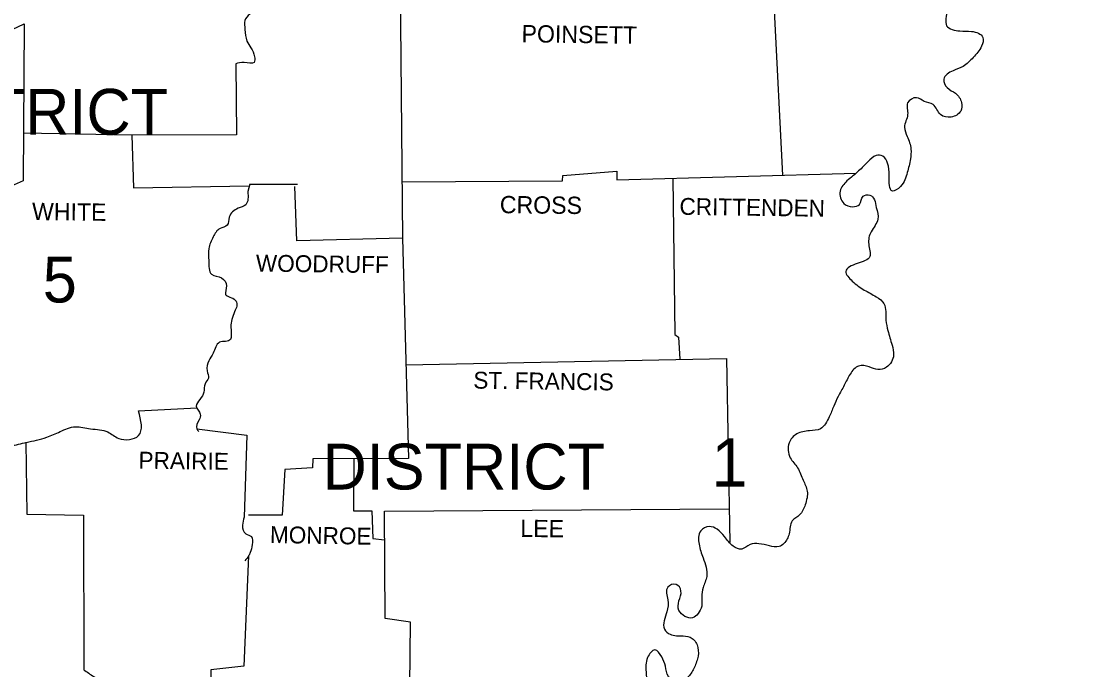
# Model space of a CAD drawing. Extents: x 3046 to 131673, y -8885 to 10756.
# Drawn here: x 105176 to 107768, y 7566 to 9143 of the extents above; entities that cross this region are included whole.
import ezdxf

# ---------------------------------------------------------------- set-up
doc = ezdxf.new("R2010")
doc.units = 0
for name, color, linetype in [('1', 7, 'Continuous'), ('2', 7, 'Continuous'), ('3', 7, 'Continuous')]:
    doc.layers.add(name, color=color, linetype=linetype)

msp = doc.modelspace()

# ---------------------------------------------------------------- linework, layer by layer
at = {"layer": '1'}
msp.add_line((105732.6, 8746.6), (105849, 8746.6), dxfattribs=at)
msp.add_line((105732.6, 8746.6), (105849, 8746.6), dxfattribs=at)
for points in [[(105635.7, 10322.8), (105632.8, 10299.3), (105652.4, 10296.4), (105651.4, 10284.6), (105673.9, 10279.7), (105675.8, 10264.1), (105686.6, 10257.2), (105689.5, 10210.3), (105745.3, 10204.4), (105745.3, 10162.3), (105765.9, 10159.4), (105765.9, 10142.7), (105783.5, 10137.9), (105782.5, 10081.1), (105798.1, 10078.2), (105802.1, 9950), (105718.9, 9942.2), (105719.9, 9914.8), (105694.4, 9913.8), (105703.2, 9408.9), (106097.5, 9400.1), (106104.4, 8615.5), (105847.1, 8608.6), (105842.2, 8740.7)], [(105635.7, 10322.8), (105632.8, 10299.3), (105652.4, 10296.4), (105651.4, 10284.6), (105673.9, 10279.7), (105675.8, 10264.1), (105686.6, 10257.2), (105689.5, 10210.3), (105745.3, 10204.4), (105745.3, 10162.3), (105765.9, 10159.4), (105765.9, 10142.7), (105783.5, 10137.9), (105782.5, 10081.1), (105798.1, 10078.2), (105802.1, 9950), (105718.9, 9942.2), (105719.9, 9914.8), (105694.4, 9913.8), (105703.2, 9408.9), (106097.5, 9400.1), (106104.4, 8615.5), (105847.1, 8608.6), (105842.2, 8740.7)], [(106992.5, 9598.7), (107009.4, 9169.2), (107029.3, 8768.4)], [(106992.5, 9598.7), (107009.4, 9169.2), (107029.3, 8768.4)], [(104637.7, 9119.3), (105140.6, 9116.4), (105183.7, 9136.9), (105180.8, 8754.4), (105151.4, 8741.7), (105125, 8719.2), (105116.2, 8710.4), (105115.2, 8600.8), (104801.1, 8598.8)], [(104637.7, 9119.3), (105140.6, 9116.4), (105183.7, 9136.9), (105180.8, 8754.4), (105151.4, 8741.7), (105125, 8719.2), (105116.2, 8710.4), (105115.2, 8600.8), (104801.1, 8598.8)], [(105698.3, 9039.1), (105700.3, 8866.9), (105445.9, 8865.9), (105181.7, 8870.9)], [(105698.3, 9039.1), (105700.3, 8866.9), (105445.9, 8865.9), (105181.7, 8870.9)], [(105445.9, 8865.9), (105449.8, 8737.8), (105731.5, 8742.8)], [(105445.9, 8865.9), (105449.8, 8737.8), (105731.5, 8742.8)], [(106103.2, 8752.4), (106493.8, 8754.4), (106494.8, 8768.1), (106625.9, 8777.9), (106625.9, 8757.3), (107208.7, 8773.3)], [(106103.2, 8752.4), (106493.8, 8754.4), (106494.8, 8768.1), (106625.9, 8777.9), (106625.9, 8757.3), (107208.7, 8773.3)], [(106762.8, 8761.1), (106767.7, 8380.6), (106776.5, 8374.8), (106779.7, 8320.6)], [(106762.8, 8761.1), (106767.7, 8380.6), (106776.5, 8374.8), (106779.7, 8320.6)], [(105732.6, 8746.6), (105727.7, 8728.9)], [(105732.6, 8746.6), (105727.7, 8728.9)], [(106104.4, 8615.5), (106119.1, 8079.3), (105886.2, 8078.3), (105885.2, 8056.8), (105817.7, 8052.9), (105811.8, 7941.3), (105729.7, 7941.3)], [(106104.4, 8615.5), (106119.1, 8079.3), (105886.2, 8078.3), (105885.2, 8056.8), (105817.7, 8052.9), (105811.8, 7941.3), (105729.7, 7941.3)], [(106112.8, 8307.2), (106893, 8322.9)], [(106112.8, 8307.2), (106893, 8322.9)], [(106893, 8322.9), (106901.2, 7874.7)], [(106893, 8322.9), (106901.2, 7874.7)], [(105461.6, 8195.7), (105603.4, 8202.6)], [(105461.6, 8195.7), (105603.4, 8202.6)], [(105603.4, 8151.7), (105725.7, 8136), (105718.9, 7936.4)], [(105603.4, 8151.7), (105725.7, 8136), (105718.9, 7936.4)], [(105187.6, 8119.4), (105189.6, 7944.3), (105327.5, 7941.3), (105328.5, 7565.6)], [(105187.6, 8119.4), (105189.6, 7944.3), (105327.5, 7941.3), (105328.5, 7565.6)], [(105986, 8078.7), (105985, 7952.1), (106030, 7952.1), (106032, 7884.6), (106060.9, 7881.6)], [(105986, 8078.7), (105985, 7952.1), (106030, 7952.1), (106032, 7884.6), (106060.9, 7881.6)], [(106116.1, 7084.2), (106192.4, 7089.1), (106191.5, 7287.8), (106120, 7292.6), (106123.9, 7681.1), (106062.3, 7689.9), (106060.4, 7951.1), (106899.7, 7957)], [(106116.1, 7084.2), (106192.4, 7089.1), (106191.5, 7287.8), (106120, 7292.6), (106123.9, 7681.1), (106062.3, 7689.9), (106060.4, 7951.1), (106899.7, 7957)], [(105729.7, 7842.5), (105717.9, 7574.4), (105637.7, 7565.6), (105639.6, 7486.4), (105671.9, 7487.3), (105672.9, 7460), (105716.9, 7455.1), (105718.4, 7407.8)], [(105729.7, 7842.5), (105717.9, 7574.4), (105637.7, 7565.6), (105639.6, 7486.4), (105671.9, 7487.3), (105672.9, 7460), (105716.9, 7455.1), (105718.4, 7407.8)]]:
    msp.add_lwpolyline(points, dxfattribs=at)
for points in [[(107630.7, 9631), (107641.5, 9632), (107674.7, 9596.8), (107689.4, 9567.4), (107710.9, 9550.8), (107735.4, 9542), (107754, 9519.5), (107766.7, 9495), (107759.8, 9473.5), (107732.4, 9471.6), (107702.1, 9466.7), (107672.8, 9467.6), (107649.3, 9448.1), (107670.8, 9421.7), (107699.2, 9397.2), (107707, 9370.8), (107691.4, 9345.3), (107660, 9331.6), (107629.7, 9319.9), (107602.3, 9296.4), (107589.6, 9273.9), (107559.3, 9264.1), (107528, 9255.3), (107500.6, 9252.4), (107469.3, 9246.5), (107438.9, 9231.8), (107426.2, 9206.4), (107430.1, 9170.2), (107429.1, 9132.1), (107461.4, 9119.3), (107489.8, 9118.4), (107517.2, 9103.7), (107514.3, 9082.2), (107493.7, 9054.8), (107469.3, 9033.2), (107444.8, 9022.5), (107422.3, 9001.9), (107430.1, 8981.4), (107450.7, 8967.7), (107465.3, 8945.2), (107463.4, 8924.6), (107439.9, 8910), (107414.5, 8915.8), (107395.9, 8940.3), (107374.4, 8948.1), (107355.8, 8956.9), (107334.2, 8944.2), (107334.2, 8915.8), (107326.4, 8885.5), (107333.3, 8863), (107342.1, 8831.7), (107341.1, 8808.2), (107333.3, 8774.9), (107316.6, 8740.7), (107297.1, 8729.9), (107289.2, 8767.1), (107285.3, 8797.4), (107273.6, 8815), (107257.9, 8816), (107237.4, 8801.3), (107214.9, 8778.8), (107186.5, 8754.4), (107169.9, 8729.9), (107178.7, 8699.6), (107200.2, 8691.8), (107216.8, 8697.6), (107225.6, 8717.2), (107242.3, 8720.1), (107257.9, 8689.8)], [(107630.7, 9631), (107641.5, 9632), (107674.7, 9596.8), (107689.4, 9567.4), (107710.9, 9550.8), (107735.4, 9542), (107754, 9519.5), (107766.7, 9495), (107759.8, 9473.5), (107732.4, 9471.6), (107702.1, 9466.7), (107672.8, 9467.6), (107649.3, 9448.1), (107670.8, 9421.7), (107699.2, 9397.2), (107707, 9370.8), (107691.4, 9345.3), (107660, 9331.6), (107629.7, 9319.9), (107602.3, 9296.4), (107589.6, 9273.9), (107559.3, 9264.1), (107528, 9255.3), (107500.6, 9252.4), (107469.3, 9246.5), (107438.9, 9231.8), (107426.2, 9206.4), (107430.1, 9170.2), (107429.1, 9132.1), (107461.4, 9119.3), (107489.8, 9118.4), (107517.2, 9103.7), (107514.3, 9082.2), (107493.7, 9054.8), (107469.3, 9033.2), (107444.8, 9022.5), (107422.3, 9001.9), (107430.1, 8981.4), (107450.7, 8967.7), (107465.3, 8945.2), (107463.4, 8924.6), (107439.9, 8910), (107414.5, 8915.8), (107395.9, 8940.3), (107374.4, 8948.1), (107355.8, 8956.9), (107334.2, 8944.2), (107334.2, 8915.8), (107326.4, 8885.5), (107333.3, 8863), (107342.1, 8831.7), (107341.1, 8808.2), (107333.3, 8774.9), (107316.6, 8740.7), (107297.1, 8729.9), (107289.2, 8767.1), (107285.3, 8797.4), (107273.6, 8815), (107257.9, 8816), (107237.4, 8801.3), (107214.9, 8778.8), (107186.5, 8754.4), (107169.9, 8729.9), (107178.7, 8699.6), (107200.2, 8691.8), (107216.8, 8697.6), (107225.6, 8717.2), (107242.3, 8720.1), (107257.9, 8689.8)], [(105878.8, 9405.1), (105861.7, 9361), (105848, 9331.6), (105839.2, 9306.2), (105820.6, 9291.5), (105814.8, 9277.8), (105798.1, 9272), (105785.4, 9252.4), (105779.5, 9234.8), (105765.9, 9227), (105759, 9205.4), (105746.3, 9193.7), (105747.3, 9174.1), (105732.6, 9160.4), (105720.8, 9144.8), (105720.8, 9123.2), (105725.7, 9094.9), (105735.5, 9078.2), (105744.3, 9056.7), (105743.3, 9043), (105718.9, 9043), (105698.3, 9039.1)], [(105878.8, 9405.1), (105861.7, 9361), (105848, 9331.6), (105839.2, 9306.2), (105820.6, 9291.5), (105814.8, 9277.8), (105798.1, 9272), (105785.4, 9252.4), (105779.5, 9234.8), (105765.9, 9227), (105759, 9205.4), (105746.3, 9193.7), (105747.3, 9174.1), (105732.6, 9160.4), (105720.8, 9144.8), (105720.8, 9123.2), (105725.7, 9094.9), (105735.5, 9078.2), (105744.3, 9056.7), (105743.3, 9043), (105718.9, 9043), (105698.3, 9039.1)], [(105727.7, 8728.9), (105722.8, 8696.7), (105704.2, 8687.9), (105682.7, 8666.3), (105677.8, 8646.8), (105660.2, 8638.9), (105643.6, 8618.4), (105632.8, 8590), (105632.8, 8560.7), (105639.6, 8527.4), (105664.1, 8518.6), (105675.8, 8499), (105673.9, 8478.5), (105697.4, 8464.8), (105701.3, 8453), (105697.4, 8440.3), (105686.6, 8404.1), (105687.6, 8379.7), (105685.6, 8368.9), (105659.2, 8362), (105643.6, 8335.6), (105632.8, 8317), (105628.9, 8292.6), (105631.8, 8275), (105624, 8261.3), (105621, 8240.7), (105611.3, 8223.1), (105602.5, 8206.5), (105612.2, 8186.9), (105609.3, 8173.2), (105603.4, 8151.7), (105608.3, 8144.8)], [(105727.7, 8728.9), (105722.8, 8696.7), (105704.2, 8687.9), (105682.7, 8666.3), (105677.8, 8646.8), (105660.2, 8638.9), (105643.6, 8618.4), (105632.8, 8590), (105632.8, 8560.7), (105639.6, 8527.4), (105664.1, 8518.6), (105675.8, 8499), (105673.9, 8478.5), (105697.4, 8464.8), (105701.3, 8453), (105697.4, 8440.3), (105686.6, 8404.1), (105687.6, 8379.7), (105685.6, 8368.9), (105659.2, 8362), (105643.6, 8335.6), (105632.8, 8317), (105628.9, 8292.6), (105631.8, 8275), (105624, 8261.3), (105621, 8240.7), (105611.3, 8223.1), (105602.5, 8206.5), (105612.2, 8186.9), (105609.3, 8173.2), (105603.4, 8151.7), (105608.3, 8144.8)], [(107257.9, 8689.8), (107261.8, 8661.4), (107245.2, 8631.1), (107239.3, 8600.8), (107242.3, 8570.4), (107211, 8553.8), (107183.6, 8534.2), (107199.2, 8510.8), (107228.6, 8489.2), (107257.9, 8472.6), (107276.5, 8456), (107281.4, 8415.9), (107286.3, 8390.4), (107296.1, 8355.2), (107300, 8330.7), (107282.4, 8301.4), (107261.8, 8295.5), (107240.3, 8302.4), (107214.9, 8304.3), (107194.3, 8284.8), (107179.6, 8257.4), (107165, 8230), (107154.2, 8206.5), (107143.4, 8181), (107121.9, 8151.7), (107095.5, 8146.8), (107064.2, 8139), (107045.6, 8117.4), (107048.5, 8081.2), (107066.2, 8056.8), (107079.9, 8026.5), (107089.6, 8000), (107084.7, 7966.8), (107071, 7942.3), (107053.4, 7927.6), (107045.6, 7896.3), (107032.9, 7872.8), (107021.1, 7865), (106997.7, 7867), (106972.2, 7871.9), (106950.7, 7869.9), (106930.2, 7859.1), (106909.6, 7866), (106888.1, 7889.5), (106870.5, 7907.1), (106850.9, 7913.9), (106830.4, 7903.2), (106826.4, 7870.9), (106836.2, 7837.6), (106845, 7792.6), (106836.2, 7765.2), (106833.3, 7720.2)], [(107257.9, 8689.8), (107261.8, 8661.4), (107245.2, 8631.1), (107239.3, 8600.8), (107242.3, 8570.4), (107211, 8553.8), (107183.6, 8534.2), (107199.2, 8510.8), (107228.6, 8489.2), (107257.9, 8472.6), (107276.5, 8456), (107281.4, 8415.9), (107286.3, 8390.4), (107296.1, 8355.2), (107300, 8330.7), (107282.4, 8301.4), (107261.8, 8295.5), (107240.3, 8302.4), (107214.9, 8304.3), (107194.3, 8284.8), (107179.6, 8257.4), (107165, 8230), (107154.2, 8206.5), (107143.4, 8181), (107121.9, 8151.7), (107095.5, 8146.8), (107064.2, 8139), (107045.6, 8117.4), (107048.5, 8081.2), (107066.2, 8056.8), (107079.9, 8026.5), (107089.6, 8000), (107084.7, 7966.8), (107071, 7942.3), (107053.4, 7927.6), (107045.6, 7896.3), (107032.9, 7872.8), (107021.1, 7865), (106997.7, 7867), (106972.2, 7871.9), (106950.7, 7869.9), (106930.2, 7859.1), (106909.6, 7866), (106888.1, 7889.5), (106870.5, 7907.1), (106850.9, 7913.9), (106830.4, 7903.2), (106826.4, 7870.9), (106836.2, 7837.6), (106845, 7792.6), (106836.2, 7765.2), (106833.3, 7720.2)], [(104800.7, 8156.5), (104857.9, 8158.5), (104911.7, 8160.5), (104945.9, 8150.7), (104985.1, 8138), (105031.1, 8132.1), (105063.4, 8119.4), (105101.5, 8099.8), (105150.4, 8108.6), (105188.6, 8118.4), (105238.5, 8131.1), (105270.8, 8144.8), (105308, 8156.6), (105345.1, 8151.7), (105387.2, 8143.9), (105413.6, 8128.2), (105461.6, 8135.1), (105461.6, 8195.7)], [(104800.7, 8156.5), (104857.9, 8158.5), (104911.7, 8160.5), (104945.9, 8150.7), (104985.1, 8138), (105031.1, 8132.1), (105063.4, 8119.4), (105101.5, 8099.8), (105150.4, 8108.6), (105188.6, 8118.4), (105238.5, 8131.1), (105270.8, 8144.8), (105308, 8156.6), (105345.1, 8151.7), (105387.2, 8143.9), (105413.6, 8128.2), (105461.6, 8135.1), (105461.6, 8195.7)], [(105718.9, 7936.4), (105715, 7916.9), (105722.8, 7896.3), (105736.5, 7889.5), (105738.5, 7869.9), (105733.6, 7850.3), (105729.7, 7842.5), (105720.8, 7830.8)], [(105718.9, 7936.4), (105715, 7916.9), (105722.8, 7896.3), (105736.5, 7889.5), (105738.5, 7869.9), (105733.6, 7850.3), (105729.7, 7842.5), (105720.8, 7830.8)], [(106833.3, 7720.2), (106810.8, 7691.8), (106777.5, 7709.4), (106777.5, 7732.9), (106782.4, 7757.4), (106770.7, 7773), (106750.1, 7766.2), (106750.1, 7735.9), (106748.2, 7706.5), (106742.3, 7664.4), (106756, 7651.7), (106787.3, 7647.8), (106809.8, 7641.9), (106823.5, 7619.4), (106822.5, 7592), (106811.8, 7565.6), (106796.1, 7544.1), (106771.7, 7536.3), (106752.1, 7549), (106744.3, 7574.4), (106735.5, 7596.9), (106718.8, 7613.6), (106701.2, 7595), (106697.3, 7560.7), (106698.3, 7531.4), (106698.3, 7491.3), (106723.7, 7464.8), (106739.4, 7434.5), (106734.5, 7407.1), (106715.9, 7374.8), (106708.1, 7346.5), (106700.2, 7308.3), (106701.2, 7266.2), (106694.4, 7225.1), (106680.7, 7197.7), (106655.2, 7175.2), (106638.6, 7160.6), (106624.9, 7145.9), (106618, 7116.5), (106613.2, 7096), (106594.6, 7071.5), (106579.9, 7069.6), (106568.1, 7079.4), (106564.2, 7096), (106564.2, 7112.6), (106556.4, 7129.3), (106531.9, 7136.1), (106512.4, 7135.1), (106503.6, 7121.4), (106516.3, 7083.3), (106521.2, 7058.8), (106514.3, 7025.5), (106518.2, 7021.6), (106483, 7003), (106454.7, 7000.1), (106431.2, 6993.3), (106408.7, 6978.6), (106397.9, 6957.1), (106382.2, 6939.4), (106368.6, 6922.8), (106350, 6915), (106329.4, 6918.9), (106302, 6921.8), (106286.4, 6902.3), (106291.3, 6873.9), (106309.8, 6857.3), (106337.2, 6849.4), (106365.6, 6851.4), (106393, 6854.3), (106418.4, 6840.6), (106413.6, 6814.2), (106389.1, 6801.5), (106352.9, 6797.6), (106323.5, 6800.5), (106288.3, 6792.7), (106270.7, 6770.2), (106280.5, 6735.9), (106318.7, 6722.2), (106336.3, 6689.9), (106337.2, 6659.6), (106324.5, 6619.5), (106306.9, 6600.9), (106272.7, 6593.1), (106246.2, 6588.2), (106242.3, 6543.2), (106230.6, 6520.7), (106210, 6513.8), (106180.7, 6528.5), (106163.1, 6535.4), (106141.6, 6545.1), (106114.2, 6561.8), (106093.6, 6558.8), (106099.5, 6515.8), (106101.4, 6513.8), (106124.9, 6481.5), (106148.4, 6456.1), (106159.2, 6425.8)], [(106833.3, 7720.2), (106810.8, 7691.8), (106777.5, 7709.4), (106777.5, 7732.9), (106782.4, 7757.4), (106770.7, 7773), (106750.1, 7766.2), (106750.1, 7735.9), (106748.2, 7706.5), (106742.3, 7664.4), (106756, 7651.7), (106787.3, 7647.8), (106809.8, 7641.9), (106823.5, 7619.4), (106822.5, 7592), (106811.8, 7565.6), (106796.1, 7544.1), (106771.7, 7536.3), (106752.1, 7549), (106744.3, 7574.4), (106735.5, 7596.9), (106718.8, 7613.6), (106701.2, 7595), (106697.3, 7560.7), (106698.3, 7531.4), (106698.3, 7491.3), (106723.7, 7464.8), (106739.4, 7434.5), (106734.5, 7407.1), (106715.9, 7374.8), (106708.1, 7346.5), (106700.2, 7308.3), (106701.2, 7266.2), (106694.4, 7225.1), (106680.7, 7197.7), (106655.2, 7175.2), (106638.6, 7160.6), (106624.9, 7145.9), (106618, 7116.5), (106613.2, 7096), (106594.6, 7071.5), (106579.9, 7069.6), (106568.1, 7079.4), (106564.2, 7096), (106564.2, 7112.6), (106556.4, 7129.3), (106531.9, 7136.1), (106512.4, 7135.1), (106503.6, 7121.4), (106516.3, 7083.3), (106521.2, 7058.8), (106514.3, 7025.5), (106518.2, 7021.6), (106483, 7003), (106454.7, 7000.1), (106431.2, 6993.3), (106408.7, 6978.6), (106397.9, 6957.1), (106382.2, 6939.4), (106368.6, 6922.8), (106350, 6915), (106329.4, 6918.9), (106302, 6921.8), (106286.4, 6902.3), (106291.3, 6873.9), (106309.8, 6857.3), (106337.2, 6849.4), (106365.6, 6851.4), (106393, 6854.3), (106418.4, 6840.6), (106413.6, 6814.2), (106389.1, 6801.5), (106352.9, 6797.6), (106323.5, 6800.5), (106288.3, 6792.7), (106270.7, 6770.2), (106280.5, 6735.9), (106318.7, 6722.2), (106336.3, 6689.9), (106337.2, 6659.6), (106324.5, 6619.5), (106306.9, 6600.9), (106272.7, 6593.1), (106246.2, 6588.2), (106242.3, 6543.2), (106230.6, 6520.7), (106210, 6513.8), (106180.7, 6528.5), (106163.1, 6535.4), (106141.6, 6545.1), (106114.2, 6561.8), (106093.6, 6558.8), (106099.5, 6515.8), (106101.4, 6513.8), (106124.9, 6481.5), (106148.4, 6456.1), (106159.2, 6425.8)], [(105328.5, 7565.6), (105353, 7549), (105378.4, 7529.4), (105385.3, 7503), (105383.3, 7484.4), (105375.5, 7468.8), (105373.5, 7444.3), (105385.3, 7426.7), (105396, 7412), (105385.3, 7385.6), (105366.7, 7361.1), (105356.9, 7333.7), (105350, 7292.6)], [(105328.5, 7565.6), (105353, 7549), (105378.4, 7529.4), (105385.3, 7503), (105383.3, 7484.4), (105375.5, 7468.8), (105373.5, 7444.3), (105385.3, 7426.7), (105396, 7412), (105385.3, 7385.6), (105366.7, 7361.1), (105356.9, 7333.7), (105350, 7292.6)]]:
    msp.add_spline(points, degree=3, dxfattribs=at)

# ---------------------------------------------------------------- texts
msp.add_text('1', height=117.4, dxfattribs=at).set_placement((106856.8, 8010.8))
msp.add_text('1', height=117.4, dxfattribs=at).set_placement((106856.8, 8010.8))
at = {"layer": '2'}
for s, height, rotation, p in [('POINSETT', 42.06, 359.1987, (106394, 9091.9)), ('POINSETT', 42.06, 359.1987, (106394, 9091.9)), ('CROSS', 42.06, 359.3839, (106341.2, 8676.1)), ('CROSS', 42.06, 359.3839, (106341.2, 8676.1)), ('CRITTENDEN', 41.09, 359.213, (106778.5, 8672.2)), ('CRITTENDEN', 41.09, 359.213, (106778.5, 8672.2)), ('WHITE', 42.07, 359.3139, (105202.3, 8659.5)), ('WHITE', 42.07, 359.3139, (105202.3, 8659.5)), ('WOODRUFF', 41.08, 359.2748, (105747.3, 8534.2)), ('WOODRUFF', 41.08, 359.2748, (105747.3, 8534.2)), ('ST. FRANCIS', 41.081, 359.2216, (106276.6, 8249.5)), ('ST. FRANCIS', 41.081, 359.2216, (106276.6, 8249.5)), ('PRAIRIE', 41.09, 359.2116, (105461.6, 8054.8)), ('PRAIRIE', 41.09, 359.2116, (105461.6, 8054.8)), ('LEE', 42.07, 359.4327, (106391.1, 7888.5)), ('LEE', 42.07, 359.4327, (106391.1, 7888.5)), ('MONROE', 41.08, 359.0331, (105781.5, 7873.8)), ('MONROE', 41.08, 359.0331, (105781.5, 7873.8))]:
    msp.add_text(s, height=height, rotation=rotation, dxfattribs=at).set_placement(p)
at = {"layer": '3'}
for s, height, p in [('DISTRICT', 111.54, (104846.1, 8866.9)), ('DISTRICT', 111.54, (104846.1, 8866.9)), ('5', 111.5, (105228.7, 8458.9)), ('5', 111.5, (105228.7, 8458.9)), ('DISTRICT', 111.54, (105909.7, 8003.9)), ('DISTRICT', 111.54, (105909.7, 8003.9))]:
    msp.add_text(s, height=height, dxfattribs=at).set_placement(p)

doc.saveas('drawing.dxf')
